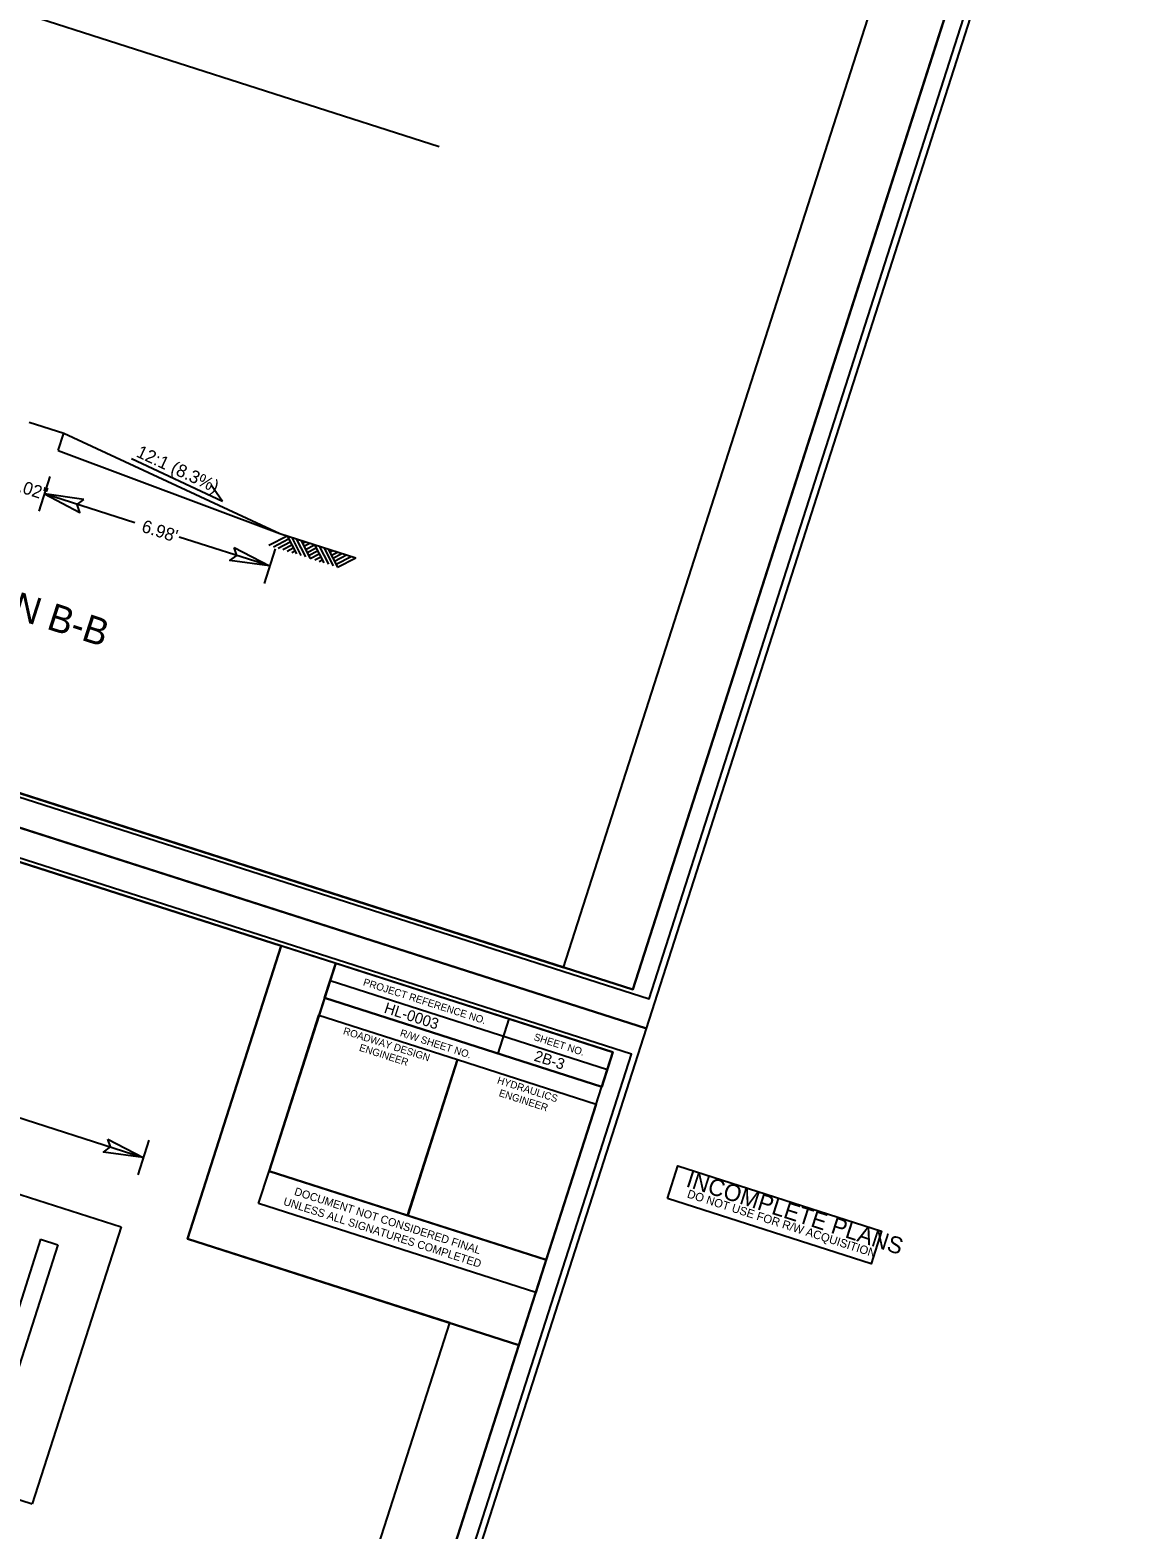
# Model space of a CAD drawing. Extents: x 928111 to 937215, y 684320 to 686530.
# Drawn here: x 933658.17 to 933688.48, y 684633.1 to 684674.31 of the extents above; entities that cross this region are included whole.
import ezdxf

# ---------------------------------------------------------------- set-up
doc = ezdxf.new("R2010")
doc.units = 0
for name, color, linetype in [('Exist Roads EOP', 7, 'Continuous'), ('Prop Conc 5in Monolithic Keyed In Island', 7, 'Continuous'), ('Prop Dimension', 7, 'Continuous'), ('Prop DSN Text', 7, 'Continuous'), ('Prop Terminator CELL', 7, 'Continuous'), ('Sheet Clip Boundary CELL', 7, 'Continuous'), ('Sheet Cutting Line CELL', 7, 'Continuous'), ('Sheet Data Field CELL', 7, 'Continuous'), ('Sheet Layout Plan Border', 7, 'Continuous'), ('Sheet Plan CELL', 7, 'Continuous'), ('Sheet Plan Layout CELL', 7, 'Continuous'), ('Sheet Plot Border Inside CELL', 7, 'Continuous'), ('Sheet Plot Border Outside CELL', 7, 'Continuous'), ('Sheet Sticker Exception Certification CELL', 7, 'Continuous'), ('Sheet Sticker Incomplete CELL', 7, 'Continuous'), ('Typical Arrow Superelevation CELL', 7, 'Continuous')]:
    doc.layers.add(name, color=color, linetype=linetype)

# ---------------------------------------------------------------- blocks, each defined once
blk = doc.blocks.new('SUPER SLOPE ARROW RIGHT')
at = {"layer": 'Typical Arrow Superelevation CELL'}
for q in [(0.077, 0.093), (3.955, 0.473)]:
    blk.add_line((4.738, 0), q, dxfattribs=at)

msp = doc.modelspace()

# ---------------------------------------------------------------- linework, layer by layer
at = {"layer": 'Exist Roads EOP'}
msp.add_line((933632.389, 684682.973), (933669.407, 684671.107), dxfattribs=at)
at = {"layer": 'Prop Conc 5in Monolithic Keyed In Island'}
for p, q in [((933618.954, 684663.916), (933665.073, 684649.133)), ((933658.144, 684663.528), (933659.096, 684663.223)), ((933658.944, 684662.747), (933659.096, 684663.223)), ((933659.096, 684663.223), (933665.037, 684660.463)), ((933658.944, 684662.747), (933665.037, 684660.463)), ((933664.734, 684660.144), (933665.232, 684660.401)), ((933664.86, 684660.104), (933665.275, 684660.318)), ((933665.037, 684660.463), (933667.118, 684659.796)), ((933665.232, 684660.401), (933665.489, 684659.903)), ((933665.358, 684660.36), (933665.614, 684659.862)), ((933665.484, 684660.32), (933665.74, 684659.822)), ((933665.61, 684660.28), (933665.866, 684659.782)), ((933664.986, 684660.064), (933665.318, 684660.235)), ((933665.112, 684660.024), (933665.361, 684660.152)), ((933665.237, 684659.983), (933665.403, 684660.069)), ((933665.363, 684659.943), (933665.446, 684659.986)), ((933665.652, 684660.197), (933665.735, 684660.239)), ((933665.695, 684660.114), (933665.861, 684660.199)), ((933665.738, 684660.031), (933665.987, 684660.159)), ((933665.78, 684659.948), (933666.029, 684660.076)), ((933665.823, 684659.865), (933666.072, 684659.993)), ((933665.866, 684659.782), (933666.115, 684659.91)), ((933665.987, 684660.159), (933666.243, 684659.661)), ((933666.112, 684660.119), (933666.369, 684659.621)), ((933666.238, 684660.078), (933666.494, 684659.58)), ((933666.364, 684660.038), (933666.62, 684659.54)), ((933666.406, 684659.955), (933666.489, 684659.998)), ((933666.449, 684659.872), (933666.615, 684659.957)), ((933666.492, 684659.789), (933666.741, 684659.917)), ((933666.534, 684659.706), (933666.866, 684659.877)), ((933665.991, 684659.742), (933666.157, 684659.827)), ((933666.117, 684659.701), (933666.2, 684659.744)), ((933666.577, 684659.623), (933666.992, 684659.837)), ((933666.62, 684659.54), (933667.118, 684659.796)), ((933622.578, 684653.617), (933660.669, 684641.408)), ((933620.136, 684645.999), (933658.227, 684633.789)), ((933660.669, 684641.408), (933658.227, 684633.789))]:
    msp.add_line(p, q, dxfattribs=at)
at = {"layer": 'Prop Dimension'}
for p, q in [((933658.715, 684662.033), (933658.41, 684661.08)), ((933661.044, 684660.761), (933658.562, 684661.557)), ((933664.752, 684659.573), (933662.268, 684660.369)), ((933664.905, 684660.049), (933664.599, 684659.096)), ((933643.24, 684649.094), (933661.279, 684643.312)), ((933661.432, 684643.788), (933661.126, 684642.836)), ((933658.459, 684641.066), (933656.627, 684635.352)), ((933658.935, 684640.913), (933657.104, 684635.199)), ((933658.459, 684641.066), (933658.935, 684640.913))]:
    msp.add_line(p, q, dxfattribs=at)
at = {"layer": 'Prop Terminator CELL'}
for points in [[(933659.648, 684661.404), (933658.562, 684661.557), (933659.538, 684661.042), (933659.465, 684661.267)], [(933663.78, 684660.079), (933664.752, 684659.573), (933663.659, 684659.721), (933663.849, 684659.862)], [(933660.307, 684643.819), (933661.279, 684643.312), (933660.186, 684643.461), (933660.376, 684643.601)]]:
    msp.add_lwpolyline(points, close=True, dxfattribs=at)
at = {"layer": 'Sheet Clip Boundary CELL'}
for points in [[(933619.504, 684665.63), (933672.831, 684648.536), (933683.069, 684680.476), (933675.86, 684682.787), (933678.442, 684690.842), (933632.324, 684705.625)], [(933606.134, 684623.92), (933659.462, 684606.826), (933669.7, 684638.766), (933662.491, 684641.077), (933665.073, 684649.133), (933618.954, 684663.916)]]:
    msp.add_lwpolyline(points, close=True, dxfattribs=at)
at = {"layer": 'Sheet Cutting Line CELL'}
for p, q in [((933610.982, 684667.415), (933675.109, 684646.86)), ((933610.982, 684667.415), (933675.109, 684646.86)), ((933675.109, 684646.86), (933610.982, 684667.415))]:
    msp.add_line(p, q, dxfattribs=at)
at = {"layer": 'Sheet Layout Plan Border'}
for points in [[(933619.504, 684665.63), (933672.831, 684648.536), (933683.069, 684680.476), (933675.86, 684682.787), (933678.442, 684690.842), (933632.324, 684705.625)], [(933606.134, 684623.92), (933659.462, 684606.826), (933669.7, 684638.766), (933662.491, 684641.077), (933665.073, 684649.133), (933618.954, 684663.916)]]:
    msp.add_lwpolyline(points, close=True, dxfattribs=at)
at = {"layer": 'Sheet Plan CELL'}
for p, q in [((933666.413, 684648.177), (933674.033, 684645.734)), ((933666.26, 684647.699), (933666.108, 684647.223)), ((933666.26, 684647.699), (933673.88, 684645.257)), ((933666.26, 684647.699), (933673.88, 684645.257)), ((933671.328, 684647.125), (933671.024, 684646.172)), ((933669.919, 684646.002), (933668.546, 684641.718))]:
    msp.add_line(p, q, dxfattribs=at)
for points in [[(933687.557, 684687.921), (933630.419, 684706.236), (933617.599, 684666.24), (933674.736, 684647.926)], [(933617.599, 684666.24), (933630.418, 684706.235), (933679.936, 684690.364), (933678.104, 684684.648), (933685.724, 684682.205), (933674.736, 684647.926)], [(933674.188, 684646.211), (933617.05, 684664.526), (933604.229, 684624.531), (933661.366, 684606.216)], [(933604.229, 684624.531), (933617.048, 684664.525), (933666.567, 684648.654), (933664.735, 684642.938), (933672.354, 684640.495), (933661.366, 684606.216)], [(933666.567, 684648.654), (933674.188, 684646.211), (933673.88, 684645.257), (933666.26, 684647.699)], [(933666.108, 684647.223), (933669.919, 684646.002), (933668.545, 684641.716), (933664.735, 684642.938)], [(933669.919, 684646.002), (933673.728, 684644.781), (933672.354, 684640.495), (933668.545, 684641.716)]]:
    msp.add_lwpolyline(points, close=True, dxfattribs=at)
at = {"layer": 'Sheet Plan Layout CELL'}
for points in [[(933630.418, 684706.235), (933617.599, 684666.24), (933674.736, 684647.926), (933684.973, 684679.865), (933675.86, 684682.787), (933678.442, 684690.842)], [(933617.048, 684664.525), (933604.229, 684624.531), (933661.366, 684606.216), (933671.604, 684638.156), (933662.491, 684641.077), (933665.073, 684649.133)], [(933662.491, 684641.077), (933671.605, 684638.156), (933674.188, 684646.211), (933665.073, 684649.133)]]:
    msp.add_lwpolyline(points, close=True, dxfattribs=at)
at = {"layer": 'Sheet Plot Border Inside CELL'}
for points in [[(933611.722, 684668.018), (933675.181, 684647.678), (933688.063, 684687.863), (933624.603, 684708.204)], [(933598.352, 684626.309), (933661.812, 684605.968), (933674.693, 684646.154), (933611.233, 684666.495)]]:
    msp.add_lwpolyline(points, close=True, dxfattribs=at)
at = {"layer": 'Sheet Plot Border Outside CELL'}
for points in [[(933610.982, 684667.415), (933675.109, 684646.86), (933688.478, 684688.57), (933624.352, 684709.125)], [(933597.613, 684625.706), (933661.739, 684605.151), (933675.109, 684646.86), (933610.982, 684667.415)]]:
    msp.add_lwpolyline(points, close=True, dxfattribs=at)
at = {"layer": 'Sheet Sticker Exception Certification CELL'}
for p, q in [((933664.448, 684642.043), (933664.735, 684642.938)), ((933664.448, 684642.043), (933664.735, 684642.938)), ((933664.735, 684642.938), (933672.354, 684640.496)), ((933664.735, 684642.938), (933672.354, 684640.496)), ((933672.068, 684639.601), (933664.448, 684642.043)), ((933672.068, 684639.601), (933664.448, 684642.043)), ((933672.354, 684640.495), (933672.067, 684639.6)), ((933672.354, 684640.495), (933672.067, 684639.6))]:
    msp.add_line(p, q, dxfattribs=at)
at = {"layer": 'Sheet Sticker Incomplete CELL'}
msp.add_lwpolyline([(933675.685, 684642.185), (933675.972, 684643.08), (933681.571, 684641.286), (933681.284, 684640.39)], close=True, dxfattribs=at)

# ---------------------------------------------------------------- block references
at = {"layer": 'Prop Conc 5in Monolithic Keyed In Island', "xscale": 0.5923542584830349, "yscale": 0.5923542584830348, "rotation": -24.032593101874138}
msp.add_blockref('SUPER SLOPE ARROW RIGHT', (933660.892, 684662.491), dxfattribs=at)

# ---------------------------------------------------------------- texts
at = {"layer": 'Prop DSN Text'}
for s, height, rotation, p in [('12:1 (8.3%)', 0.35, 335.0825, (933661.062, 684662.59)), ('1.02"', 0.35, 342.2272, (933657.567, 684661.698)), ("6.98'", 0.35, 342.2272, (933661.208, 684660.521)), ('SECTION B-B', 0.75, 342.2273, (933654.082, 684659.3))]:
    msp.add_text(s, height=height, rotation=rotation, dxfattribs=at).set_placement(p)
at = {"layer": 'Sheet Data Field CELL'}
for s, p in [('HL-0003', (933667.877, 684647.297)), ('2B-3', (933671.997, 684645.979))]:
    msp.add_text(s, height=0.3, rotation=342.2273, dxfattribs=at).set_placement(p)
at = {"layer": 'Sheet Plan CELL'}
for s, p in [('PROJECT REFERENCE NO.', (933667.306, 684648.051)), ('ROADWAY DESIGN', (933666.757, 684646.709)), ('R/W SHEET NO.', (933668.319, 684646.653)), ('SHEET NO.', (933671.996, 684646.543)), ('ENGINEER', (933667.197, 684646.251)), ('HYDRAULICS', (933670.99, 684645.353)), ('ENGINEER', (933671.036, 684645.003))]:
    msp.add_text(s, height=0.2, rotation=342.2273, dxfattribs=at).set_placement(p)
at = {"layer": 'Sheet Sticker Exception Certification CELL'}
for s, p in [('UNLESS ALL SIGNATURES COMPLETED', (933665.111, 684642.014)), ('UNLESS ALL SIGNATURES COMPLETED', (933665.111, 684642.014)), ('DOCUMENT NOT CONSIDERED FINAL', (933665.411, 684642.287)), ('DOCUMENT NOT CONSIDERED FINAL', (933665.411, 684642.287))]:
    msp.add_text(s, height=0.22, rotation=342.2273, dxfattribs=at).set_placement(p)
at = {"layer": 'Sheet Sticker Incomplete CELL'}
for s, height, p in [('INCOMPLETE PLANS', 0.4608, (933676.169, 684642.522)), ('DO NOT USE FOR R/W ACQUISITION', 0.2304, (933676.208, 684642.217))]:
    msp.add_text(s, height=height, rotation=342.2273, dxfattribs=at).set_placement(p)

doc.saveas('drawing.dxf')
